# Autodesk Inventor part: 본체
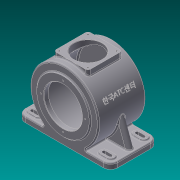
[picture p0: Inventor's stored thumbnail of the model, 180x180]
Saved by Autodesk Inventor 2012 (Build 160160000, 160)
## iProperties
Created: 2015-06
Part Number: 본체
Material: 알루미늄-6061
Document SubType Name: Modeling
Designer: Administrator
Density: 2.71 g/cm^3
Mass: 3275.65 g
Surface Area: 2298.92 cm^2
Volume: 1208.73 cm^3
Author: Administrator
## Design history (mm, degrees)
sketch "스케치1"
  geometry: L1 (-115, -71)-(-46.733, -71); L2 (-115, -71)-(-115, -85); L3 (-115, -85)-(115, -85); L4 (115, -85)-(115, -71); L5 (-46.733, -71)-(46.733, -71); L6 (46.733, -71)-(115, -71); A1 r 85 centre (0, 0) between (46.733, -71) and (-46.733, -71); 2 further points
  constraints: 12 end point, 4 perpendicular, 3 horizontal, 2 point on circle, 1 centre point, 1 coincident, 1 parallel, 1 point on line, 1 vertical alignment
  dimensions: "d0" = 170 diameter of A1; "d15" = 230 distance between parallel lines of L4 L2; "d16" = 14 distance between parallel lines of L3 L1; "d17" = 85 distance from line of L3 point (0, 0); "d19" = 115 horizontal distance of point (0, 0) L1.start
extrude "돌출4" new body sketch "스케치1" stored distance "d20" = 118; taper "d21" = 0 deg
sketch "스케치5"
  geometry: C1 r 65 at (0, 0); A1 r 85 centre (0, 0) between (46.733, -71) and (-46.733, -71) reference
  constraints: 1 centre point, 1 coincident
  dimensions: "d22" = 130 diameter of C1
extrude "돌출5" join sketch "스케치5" distance "d23" = 3; taper "d24" = 0 deg
hole "구멍1" diameter "d27" = 95; stored, may be unused: countersink angle "d31" = 90 deg, drill point angle "d33" = 0 deg; dims "d25" = 10, "d26" = 10, "d28" = 6, "d29" = 4, "d30" = 2, "d32" = 11
sketch "스케치6"
  geometry: C1 r 65 at (0, 0); A1 r 85 centre (0, 0) between (-46.733, 71) and (46.733, 71) reference
  constraints: 1 centre point, 1 coincident
  dimensions: "d34" = 130 diameter of C1
extrude "돌출6" join sketch "스케치6" distance "d35" = 13; taper "d36" = 0 deg
hole "구멍2" diameter "d39" = 154; stored, may be unused: countersink angle "d43" = 90 deg, drill point angle "d45" = 0 deg; dims "d37" = 10, "d38" = 10, "d40" = 6, "d41" = 4, "d42" = 2, "d44" = 102
sketch "스케치7"
  geometry: C1 r 77 at (0, 0) reference; C2 r 31 at (0, 0)
  constraints: 1 centre point, 1 coincident
  dimensions: "d46" = 62 diameter of C2
extrude "돌출7" join sketch "스케치7" distance "d47" = 3.5; taper "d48" = 0 deg
hole "구멍3" diameter "d51" = 47; stored, may be unused: countersink angle "d55" = 90 deg, drill point angle "d57" = 0 deg; dims "d49" = 10, "d50" = 10, "d52" = 6, "d53" = 4, "d54" = 2, "d56" = 14
hole "구멍4" diameter "d60" = 30; stored, may be unused: countersink angle "d64" = 90 deg, drill point angle "d66" = 0 deg; dims "d58" = 10, "d59" = 10, "d61" = 6, "d62" = 4, "d63" = 2, "d65" = 3
node "작업 평면3"
sketch "스케치8"
  geometry: L1 (-42.5, 42.5)-(42.5, 42.5); L2 (42.5, 42.5)-(42.5, -42.5); L3 (42.5, -42.5)-(-42.5, -42.5); L4 (-42.5, -42.5)-(-42.5, 42.5); L5 (-42.5, -42.5)-(42.5, 42.5); 2 further points
  constraints: 10 end point, 2 parallel, 2 perpendicular, 1 coincident, 1 horizontal, 1 midpoint
  dimensions: "d68" = 85 distance between parallel lines of L4 L2
extrude "돌출8" join sketch "스케치8" stored distance "d69" = 3.5; taper "d70" = 0 deg
hole "구멍5" diameter "d73" = 70; stored, may be unused: countersink angle "d77" = 90 deg, drill point angle "d79" = 0 deg; dims "d71" = 42.5, "d72" = 42.5, "d74" = 6, "d75" = 4, "d76" = 2, "d78" = 3
sketch "스케치9"
  geometry: L1 (42.5, 88)-(42.5, 73.612) reference; L2 (46.733, -71)-(115, -71) reference; L3 (115, -71)-(115, -85) reference; L4 (115, -85)-(-115, -85) reference; L5 (-115, -85)-(-115, -71) reference; L6 (-115, -71)-(-46.733, -71) reference; L7 (-42.5, 73.612)-(-42.5, 88) reference; L8 (-42.5, 88)-(-35, 88) reference; L9 (-35, 88)-(-35, 68.586) reference; L10 (35, 68.586)-(35, 88) reference; L11 (35, 88)-(42.5, 88) reference; L12 (-84.87, -4.703)-(-109, -71); A1 r 85 centre (0, 0) between (46.733, -71) and (42.5, 73.612) reference; A2 r 85 centre (0, 0) between (-42.5, 73.612) and (-46.733, -71) reference; A3 r 77 centre (0, 0) between (-35, 68.586) and (35, 68.586) reference; 1 further point
  constraints: 2 end point, 1 point on circle, 1 point on line
  dimensions: "d80" = 6 distance from line of L12.end L5; "d81" = 110 deg angle of L6 L12
feature "리브1" sketch "스케치9" dims "d82" = 1, "d83" = 15, "d84" = 0, "d85" = 0, "d86" = 1, "d87" = 1
sketch "스케치10"
  geometry: L1 (68.267, 0)-(0, 0) reference; L2 (34.267, -9)-(50.267, -9); L3 (34.267, -27)-(50.267, -27); L4 (-161.733, -118)-(-161.733, 0) reference; L5 (-161.733, 0)-(-93.467, 0) reference; L6 (-93.467, -118)-(-93.467, 0) reference; L7 (0, -118)-(-93.467, -118) reference; L8 (0, -66.5)-(0, -118) reference; L9 (62.267, -66.5)-(0, -66.5) reference; L10 (62.267, -51.5)-(62.267, -66.5) reference; L11 (0, -51.5)-(62.267, -51.5) reference; L12 (0, 0)-(0, -51.5) reference; L13 (0, 0)-(68.267, 0) reference; L14 (68.267, 0)-(68.267, -118) reference; L15 (68.267, -118)-(0, -118) reference; L16 (-93.467, -118)-(-161.733, -118) reference; L17 (-93.467, 0)-(0, 0) reference; L18 (-76.533, -8)-(-76.533, -110) reference; L19 (-76.533, -110)-(-16.934, -110) reference; L20 (-16.934, -110)-(-16.934, -8) reference; L21 (-16.934, -8)-(-76.533, -8) reference; L22 (34.267, -91)-(50.267, -91); L23 (34.267, -109)-(50.267, -109); L24 (-143.733, -109)-(-127.733, -109); L25 (-143.733, -91)-(-127.733, -91); L26 (-143.733, -9)-(-127.733, -9); L27 (-143.733, -27)-(-127.733, -27); A1 r 9 centre (50.267, -18) between (50.267, -27) and (50.267, -9); A2 r 9 centre (34.267, -18) between (34.267, -9) and (34.267, -27); A3 r 9 centre (-127.733, -18) between (-127.733, -27) and (-127.733, -9); A4 r 9 centre (-143.733, -18) between (-143.733, -9) and (-143.733, -27); A5 r 9 centre (-127.733, -100) between (-127.733, -109) and (-127.733, -91); A6 r 9 centre (-143.733, -100) between (-143.733, -91) and (-143.733, -109); A7 r 9 centre (50.267, -100) between (50.267, -109) and (50.267, -91); A8 r 9 centre (34.267, -100) between (34.267, -91) and (34.267, -109); 1 further point
  constraints: 16 end point, 16 point on circle, 16 tangent, 8 centre point, 6 horizontal alignment, 5 equal length, 4 equal radius, 2 vertical alignment
  dimensions: "d88" = 18 diameter of A1; "d89" = 16 distance of A1.centre A2.centre; "d90" = 97 horizontal distance of A1.centre point (-46.733, -59); "d91" = 18 distance from line of L1 A1.centre; "d99" = 18 diameter of A3; "d100" = 16 distance of A3.centre A4.centre; "d101" = 18 diameter of A5; "d102" = 16 distance of A5.centre A6.centre; "d103" = 18 diameter of A7; "d104" = 16 distance of A7.centre A8.centre; "d105" = 18 distance from line of L15 A7.centre; "d108" = 97 horizontal distance of point (-46.733, -59) A6.centre (= d90)
extrude "돌출11" join sketch "스케치10" distance "d109" = 3; taper "d110" = 0 deg
sketch "스케치12"
  geometry: L1 (50.267, -109)-(34.267, -109) reference; L2 (34.267, -91)-(50.267, -91) reference; L3 (34.267, -9)-(50.267, -9) reference; L4 (50.267, -27)-(34.267, -27) reference; L5 (-127.733, -109)-(-143.733, -109) reference; L6 (-143.733, -91)-(-127.733, -91) reference; L7 (-127.733, -27)-(-143.733, -27) reference; L8 (-143.733, -9)-(-127.733, -9) reference; L9 (4.267, -66.5)-(4.267, -118) reference; L10 (4.267, -118)-(-97.733, -118) reference; L11 (-97.733, -118)-(-97.733, 0) reference; L12 (-97.733, 0)-(4.267, 0) reference; L13 (4.267, 0)-(4.267, -51.5) reference; L14 (4.267, -51.5)-(61.175, -51.5) reference; L15 (61.175, -51.5)-(61.175, -66.5) reference; L16 (61.175, -66.5)-(4.267, -66.5) reference; L17 (-82.858, -8)-(-82.858, -110) reference; L18 (-82.858, -110)-(-10.609, -110) reference; L19 (-10.609, -110)-(-10.609, -8) reference; L20 (-10.609, -8)-(-82.858, -8) reference; L21 (-127.733, -14)-(-143.733, -14); L22 (-143.733, -22)-(-127.733, -22); L23 (50.267, -14)-(34.267, -14); L24 (34.267, -22)-(50.267, -22); L25 (50.267, -96)-(34.267, -96); L26 (34.267, -104)-(50.267, -104); L27 (-143.733, -100)-(-127.733, -100); L28 (-143.733, -96)-(-127.733, -96); L29 (-143.733, -104)-(-127.733, -104); A1 r 9 centre (34.267, -100) between (34.267, -91) and (34.267, -109) reference; A2 r 9 centre (50.267, -100) between (50.267, -109) and (50.267, -91) reference; A3 r 9 centre (50.267, -18) between (50.267, -27) and (50.267, -9) reference; A4 r 9 centre (34.267, -18) between (34.267, -9) and (34.267, -27) reference; A5 r 9 centre (-143.733, -100) between (-143.733, -91) and (-143.733, -109) reference; A6 r 9 centre (-127.733, -100) between (-127.733, -109) and (-127.733, -91) reference; A7 r 9 centre (-143.733, -18) between (-143.733, -9) and (-143.733, -27) reference; A8 r 9 centre (-127.733, -18) between (-127.733, -27) and (-127.733, -9) reference; A9 r 4 centre (-143.733, -18) between (-143.733, -14) and (-143.733, -22); A10 r 4 centre (-127.733, -18) between (-127.733, -22) and (-127.733, -14); A11 r 4 centre (34.267, -18) between (34.267, -14) and (34.267, -22); A12 r 4 centre (50.267, -18) between (50.267, -22) and (50.267, -14); A13 r 4 centre (34.267, -100) between (34.267, -96) and (34.267, -104); A14 r 4 centre (50.267, -100) between (50.267, -104) and (50.267, -96); A15 r 4 centre (-143.733, -100) between (-143.733, -96) and (-143.733, -104); A16 r 4 centre (-127.733, -100) between (-127.733, -104) and (-127.733, -96); 1 further point
  constraints: 18 end point, 16 point on circle, 8 centre point, 2 coincident, 2 parallel, 2 tangent, 9 other
  dimensions: "d111" = 5 distance between parallel lines of L8 L21; "d114" = 5 distance between parallel lines of L3 L23; "d115" = 5 distance between parallel lines of L2 L25; "d116" = 8 diameter of A15; "d117" = 8 diameter of A16; "d118" = 16 distance of L29.start L29.end
extrude "돌출12" cut sketch "스케치12" stored distance "d119" = 3; taper "d120" = 0 deg
node "작업 평면5"
  node "작업 평면4"
sketch "스케치13"
  geometry: L1 (-40.533, 6.549)-(40.533, 6.549); L2 (40.533, 6.549)-(40.533, -6.549); L3 (40.533, -6.549)-(-40.533, -6.549); L4 (-40.533, -6.549)-(-40.533, 6.549); L5 (-40.533, -6.549)-(40.533, 6.549); 2 further points
  constraints: 2 end point, 1 coincident, 1 midpoint, 2 other
feature "엠보싱1" sketch "스케치13" dims "d27" = 95, "d29" = 4, "d30" = 2, "d32" = 11, "d123" = 0.5, "d124" = 0
sketch "스케치14" dims "d125" = 110
  geometry: C1 r 47.5 at (0, 0) reference; C2 r 65 at (0, 0) reference; 2 further points
  constraints: 2 vertical alignment, 1 coincident, 2 other
hole "구멍6" sketch "스케치14" at (0, 55) diameter "d126" = 3.242; stored, may be unused: countersink angle "d130" = 90 deg, drill point angle "d132" = 118 deg; dims "d127" = 6, "d128" = 4, "d129" = 2, "d131" = 3
sketch "스케치15"
  geometry: L1 (0, 0)-(-35, 0); L2 (0, 0)-(0, 35); A1 r 35 centre (0, 0) between (-35, 0) and (0, 35) reference; 4 further points
  constraints: 4 end point, 2 point on circle, 2 symmetric about line, 1 horizontal alignment, 1 perpendicular, 1 vertical, 1 vertical alignment
  dimensions: "d136" = 71 distance of point (-35.5, -35.5) point (-35.5, 35.5); "d137" = 71 distance of point (-35.5, 35.5) point (35.5, 35.5)
hole "구멍7" sketch "스케치15" at (-35.5, 35.5), (35.5, 35.5), (35.5, -35.5), (-35.5, -35.5) diameter "d138" = 3.242; stored, may be unused: countersink angle "d142" = 90 deg, drill point angle "d144" = 118 deg; dims "d139" = 10, "d140" = 4, "d141" = 2, "d143" = 13
fillet "모깎기1" dims "d145" = 18
fillet "모깎기2" dims "d146" = 7
feature "면 기울기1" dims angle "d147" = 25 deg
fillet "모깎기3" dims "d148" = 0.3
fillet "모깎기4" dims "d149" = 3
chamfer "모따기1" distance "d150" = 1; stored, may be unused: second distance "d151" = 2, angle "d152" = 45 deg
fillet "모깎기5" dims "d153" = 7.5
fillet "모깎기6" dims "d154" = 3
fillet "모깎기7" dims "d155" = 3
fillet "모깎기8" dims "d156" = 3
fillet "모깎기9" dims "d157" = 3
node "솔리드2"
pattern_circular "원형 패턴1" dims angle "d134" = 360 deg
mirror "대칭2"
node "절단 모서리 투영2"
node "절단 모서리 투영3"
node "절단 모서리 투영4"
other parameters: "d67" = 88, "d121" = -25 deg, "d122" = 85
